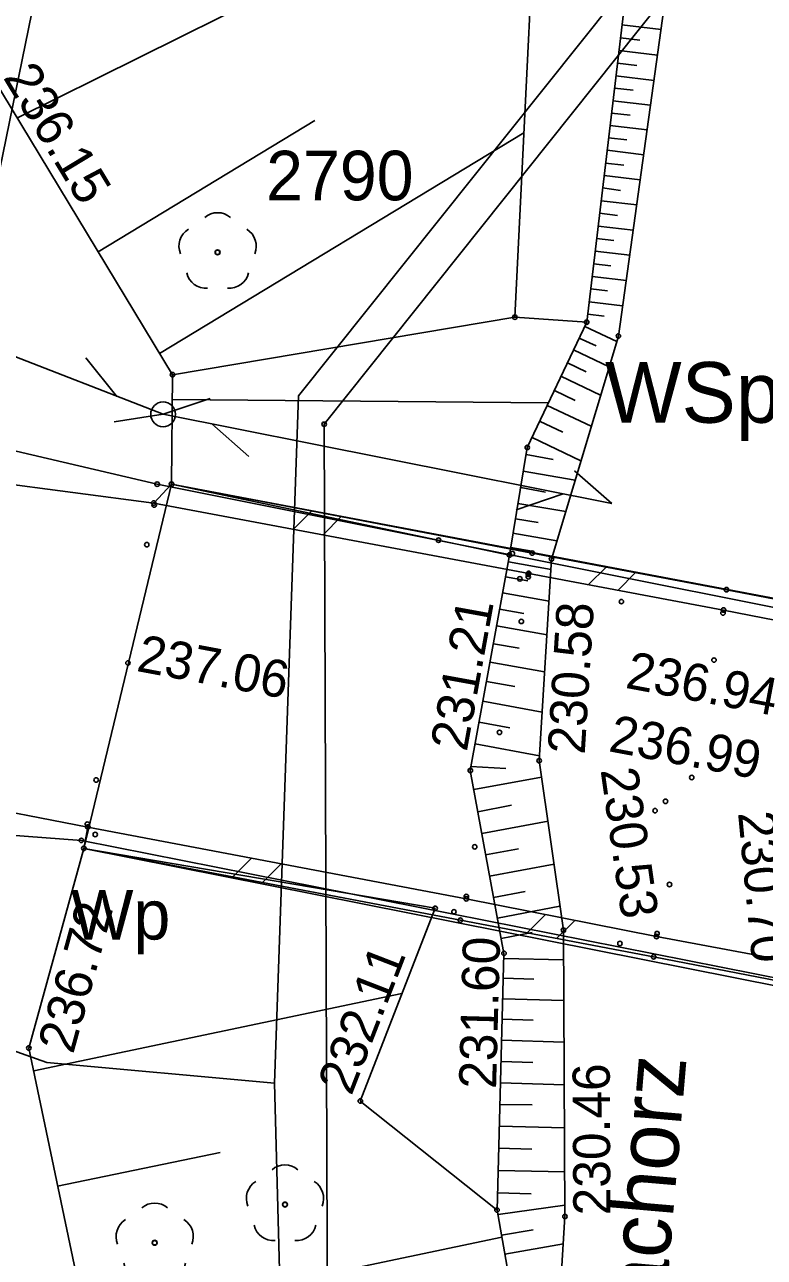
# Model space of a CAD drawing. Extents: x 6596400 to 6597200, y 5539751 to 5540251.
# Drawn here: x 6596725.66 to 6596740.59, y 5540079.28 to 5540104.16 of the extents above; entities that cross this region are included whole.
import ezdxf

# ---------------------------------------------------------------- set-up
doc = ezdxf.new("R2010")
doc.units = 0
for name, color, linetype in [('000 Inne (niezydentyfikowane)', 7, 'Continuous'), ('140-Punkty robocze', 7, 'Continuous'), ('203-punkt graniczny', 7, 'Continuous'), ('210-oznaczenie konturu użytku gruntowego', 7, 'Continuous'), ('211-numer działki ewidencyjnej', 7, 'Continuous'), ('218-kontur użytku gruntowego', 7, 'Continuous'), ('219-działka ewidencyjna', 7, 'Continuous'), ('bariera ochronna', 7, 'Continuous'), ('drzewo liściaste', 7, 'Continuous'), ('jezdnia', 7, 'Continuous'), ('Linia obszaru zagospodarowania terenu', 7, 'Continuous'), ('most', 7, 'Continuous'), ('Opis obszaru zagospodarowania terenu', 7, 'Continuous'), ('pikieta sztuczna', 7, 'Continuous'), ('pikieta sztuczna-Atr2', 7, 'Continuous'), ('przewód telekomunikacyjny napowietrzny', 7, 'Continuous'), ('skarpa nieumocniona', 7, 'Continuous'), ('skarpa umocniona', 7, 'Continuous'), ('słup przewodów napowietrznych', 7, 'Continuous'), ('woda płynąca', 7, 'Continuous'), ('woda płynąca-Atr103', 7, 'Continuous'), ('ściana oporowa (poligon)', 7, 'Continuous')]:
    doc.layers.add(name, color=color, linetype=linetype)

# ---------------------------------------------------------------- blocks, each defined once
blk = doc.blocks.new('203')
blk.add_circle((0, 0), 0.045)
blk = doc.blocks.new('SUTP')
for p, q in [((0, 0), (0.866, 0.5)), ((9.232, 0), (8.366, 0.5)), ((0, 0), (9.232, 0)), ((1.866, -0.5), (1, 0)), ((7.366, -0.5), (8.232, 0))]:
    blk.add_line(p, q)
blk = doc.blocks.new('US15')
blk.add_circle((0, 0), 0.25)
blk = doc.blocks.new('OP021')
blk.add_circle((0, 0), 0.05)
for centre, start, end in [((0, 0.4), 49.272, 130.728), ((-0.38, 0.124), 121.308, 202.548), ((0.38, 0.124), 337.452, 58.692), ((-0.235, -0.324), 193.221, 274.871), ((0.235, -0.324), 265.129, 346.779)]:
    blk.add_arc(centre, 0.4, start, end)
blk = doc.blocks.new('PIKIETA')
blk.add_circle((0, 0), 0.045)
blk = doc.blocks.new('PW01')
blk.add_circle((0, 0), 0.045)

msp = doc.modelspace()

# ---------------------------------------------------------------- linework, layer by layer
at = {"layer": '000 Inne (niezydentyfikowane)'}
for p, q in [((6596725.5, 5540102.27), (6596736, 5540107.48)), ((6596737.71, 5540104.15), (6596738.5, 5540104.06)), ((6596737.68, 5540103.89), (6596738.07, 5540103.84)), ((6596737.65, 5540103.63), (6596738.43, 5540103.54)), ((6596737.62, 5540103.38), (6596738.01, 5540103.33)), ((6596737.59, 5540103.12), (6596738.36, 5540103.03)), ((6596737.56, 5540102.87), (6596737.94, 5540102.83)), ((6596737.53, 5540102.62), (6596738.29, 5540102.53)), ((6596737.5, 5540102.37), (6596737.88, 5540102.33)), ((6596727.14, 5540099.57), (6596731.51, 5540102.22)), ((6596737.47, 5540102.12), (6596738.22, 5540102.03)), ((6596728.38, 5540097.52), (6596735.73, 5540101.97)), ((6596737.44, 5540101.87), (6596737.81, 5540101.83)), ((6596737.41, 5540101.62), (6596738.15, 5540101.53)), ((6596737.38, 5540101.36), (6596737.75, 5540101.32)), ((6596737.35, 5540101.11), (6596738.08, 5540101.02)), ((6596737.32, 5540100.86), (6596737.68, 5540100.81)), ((6596737.29, 5540100.6), (6596738.01, 5540100.52)), ((6596737.26, 5540100.35), (6596737.62, 5540100.3)), ((6596737.23, 5540100.09), (6596737.94, 5540100.01)), ((6596737.2, 5540099.84), (6596737.55, 5540099.8)), ((6596737.17, 5540099.58), (6596737.87, 5540099.5)), ((6596737.14, 5540099.33), (6596737.49, 5540099.29)), ((6596737.11, 5540099.07), (6596737.8, 5540098.99)), ((6596737.08, 5540098.82), (6596737.42, 5540098.78)), ((6596737.05, 5540098.56), (6596737.72, 5540098.48)), ((6596737.02, 5540098.31), (6596737.35, 5540098.27)), ((6596736.96, 5540098.06), (6596737.61, 5540097.76)), ((6596736.85, 5540097.83), (6596737.19, 5540097.67)), ((6596736.73, 5540097.59), (6596737.45, 5540097.25)), ((6596736.61, 5540097.33), (6596736.99, 5540097.15)), ((6596736.48, 5540097.06), (6596737.28, 5540096.68)), ((6596736.35, 5540096.77), (6596736.77, 5540096.57)), ((6596736.2, 5540096.47), (6596737.09, 5540096.05)), ((6596736.05, 5540096.15), (6596736.52, 5540095.93)), ((6596735.9, 5540095.82), (6596736.88, 5540095.35)), ((6596735.78, 5540095.48), (6596736.32, 5540095.38)), ((6596735.72, 5540095.14), (6596736.77, 5540094.96)), ((6596735.67, 5540094.81), (6596736.17, 5540094.72)), ((6596735.61, 5540094.49), (6596736.58, 5540094.33)), ((6596735.56, 5540094.18), (6596736.02, 5540094.11)), ((6596735.51, 5540093.89), (6596736.4, 5540093.74)), ((6596735.47, 5540093.6), (6596735.89, 5540093.53)), ((6596735.42, 5540093.31), (6596736.28, 5540093.16)), ((6596735.36, 5540093.01), (6596735.81, 5540092.93)), ((6596735.3, 5540092.69), (6596736.24, 5540092.52)), ((6596735.24, 5540092.36), (6596735.73, 5540092.27)), ((6596735.18, 5540092.02), (6596736.2, 5540091.84)), ((6596735.12, 5540091.66), (6596735.64, 5540091.57)), ((6596735.05, 5540091.29), (6596736.15, 5540091.09)), ((6596734.98, 5540090.9), (6596735.55, 5540090.8)), ((6596734.9, 5540090.5), (6596736.1, 5540090.28)), ((6596734.83, 5540090.08), (6596735.45, 5540089.96)), ((6596734.75, 5540089.64), (6596736.05, 5540089.4)), ((6596734.66, 5540089.18), (6596735.37, 5540089.14)), ((6596734.72, 5540088.72), (6596736.09, 5540088.97)), ((6596734.8, 5540088.27), (6596735.48, 5540088.4)), ((6596734.88, 5540087.83), (6596736.22, 5540088.08)), ((6596734.96, 5540087.4), (6596735.62, 5540087.52)), ((6596735.04, 5540086.97), (6596736.34, 5540087.21)), ((6596735.12, 5540086.54), (6596735.76, 5540086.66)), ((6596735.2, 5540086.12), (6596736.46, 5540086.36)), ((6596735.27, 5540085.71), (6596735.9, 5540085.83)), ((6596735.33, 5540085.31), (6596736.53, 5540085.28)), ((6596735.32, 5540084.91), (6596735.93, 5540084.89)), ((6596725.84, 5540083.04), (6596733.27, 5540084.6)), ((6596735.31, 5540084.49), (6596736.54, 5540084.46)), ((6596735.29, 5540084.08), (6596735.92, 5540084.06)), ((6596735.28, 5540083.66), (6596736.54, 5540083.62)), ((6596735.27, 5540083.23), (6596735.91, 5540083.21)), ((6596735.26, 5540082.8), (6596736.55, 5540082.76)), ((6596735.25, 5540082.36), (6596735.9, 5540082.35)), ((6596735.24, 5540081.92), (6596736.55, 5540081.89)), ((6596726.32, 5540080.71), (6596729.6, 5540081.39)), ((6596735.22, 5540081.48), (6596735.89, 5540081.46)), ((6596735.21, 5540081.03), (6596736.56, 5540081)), ((6596735.2, 5540080.58), (6596735.88, 5540080.56)), ((6596735.21, 5540080.14), (6596736.56, 5540080.33)), ((6596726.91, 5540077.93), (6596735.29, 5540079.68)), ((6596735.28, 5540079.72), (6596735.92, 5540079.83)), ((6596735.35, 5540079.34), (6596736.53, 5540079.55))]:
    msp.add_line(p, q, dxfattribs=at)
msp.add_lwpolyline([(6596728.64, 5540096.59), (6596736.23, 5540096.52)], dxfattribs=at)
at = {"layer": '218-kontur użytku gruntowego'}
for points in [[(6596727.34, 5540111.95), (6596725.02, 5540100.61)], [(6596725.02, 5540100.61), (6596727.34, 5540111.95)], [(6596742.6, 5540109.76), (6596731.7, 5540096.09)], [(6596731.7, 5540096.09), (6596742.6, 5540109.76)], [(6596731.7, 5540096.09), (6596731.78, 5540074)], [(6596731.78, 5540074), (6596731.7, 5540096.09)]]:
    msp.add_lwpolyline(points, dxfattribs=at)
at = {"layer": '219-działka ewidencyjna'}
for points in [[(6596725.02, 5540100.61), (6596727.34, 5540111.95)], [(6596731.7, 5540096.09), (6596742.6, 5540109.76)], [(6596731.78, 5540074), (6596731.7, 5540096.09)]]:
    msp.add_lwpolyline(points, dxfattribs=at)
at = {"layer": 'bariera ochronna'}
for points in [[(6596724.82, 5540100.27), (6596724.21, 5540095.84), (6596728.33, 5540094.88), (6596750, 5540090.55), (6596759.32, 5540088.76), (6596768.42, 5540087.04), (6596777.66, 5540085.28), (6596786.8, 5540083.5), (6596789.01, 5540083.12), (6596792.87, 5540082.26), (6596795.36, 5540081.78), (6596800.78, 5540080.9), (6596809.14, 5540079.91)], [(6596724.95, 5540083.06), (6596725.29, 5540087.8), (6596726.8, 5540087.69), (6596748.55, 5540083.38), (6596760.42, 5540081.05)]]:
    msp.add_lwpolyline(points, dxfattribs=at)
at = {"layer": 'jezdnia'}
for points in [[(6596653.124, 5540120.82), (6596653.79, 5540120.41), (6596660.56, 5540116.72), (6596663.8, 5540114.85), (6596668, 5540112.34), (6596669.54, 5540111.42), (6596675.97, 5540107.49), (6596679.93, 5540105.19), (6596682.35, 5540103.89), (6596691.43, 5540099.24), (6596702.2, 5540094.56), (6596706.34, 5540093.02), (6596710.59, 5540091.59), (6596715.92, 5540090.16), (6596720.02, 5540089.23), (6596724.29, 5540088.47), (6596726.93, 5540087.96), (6596734.57, 5540086.51), (6596738.41, 5540085.75), (6596741.83, 5540085.11), (6596743.38, 5540084.84), (6596743.64, 5540085.7), (6596748.72, 5540084.9)], [(6596828.719, 5540062.578), (6596825.42, 5540065.32), (6596821.78, 5540067.97), (6596818.46, 5540070.24), (6596813.26, 5540073.35), (6596810.44, 5540074.77), (6596805.94, 5540076.86), (6596804.14, 5540077.61), (6596801.52, 5540078.62), (6596798.28, 5540079.76), (6596795.16, 5540080.71), (6596792.67, 5540081.35), (6596788.77, 5540082.14), (6596786.6, 5540082.54), (6596777.46, 5540084.34), (6596768.21, 5540086.12), (6596759.17, 5540087.8), (6596749.8, 5540089.83), (6596749.82, 5540090.44), (6596743.18, 5540091.67), (6596739.76, 5540092.34), (6596735.83, 5540093.08), (6596728.26, 5540094.5), (6596723.35, 5540095.14)]]:
    msp.add_lwpolyline(points, dxfattribs=at)
at = {"layer": 'Linia obszaru zagospodarowania terenu'}
for points in [[(6596664.616, 5540132.112), (6596671.21, 5540127.95), (6596681.8, 5540121.54), (6596690.35, 5540115.69), (6596701.61, 5540105.97), (6596709.34, 5540098.61), (6596715.39, 5540091.82), (6596718.63, 5540088.53), (6596721.87, 5540084.71), (6596726.1, 5540083.21), (6596730.7, 5540082.79), (6596730.91, 5540075), (6596745.51, 5540074.64), (6596746.77, 5540082.74), (6596765.15, 5540085.09), (6596776.62, 5540086.27), (6596789.34, 5540086.1), (6596798.37, 5540085.54), (6596805.65, 5540083.56), (6596813.11, 5540081.53), (6596819.41, 5540077.54), (6596826.58, 5540072.81), (6596832.721, 5540067.998)], [(6596781.725, 5540112.112), (6596780.93, 5540109.34), (6596777.59, 5540106.98), (6596766.77, 5540110.34), (6596752.84, 5540119.06), (6596742.54, 5540110.89), (6596731.18, 5540096.66), (6596730.7, 5540082.79)]]:
    msp.add_lwpolyline(points, dxfattribs=at)
at = {"layer": 'most'}
msp.add_lwpolyline([(6596728.62, 5540094.88), (6596726.85, 5540087.53), (6596748.43, 5540083.24), (6596749.89, 5540090.85)], close=True, dxfattribs=at)
at = {"layer": 'skarpa nieumocniona'}
for points in [[(6596751.79, 5540118.27), (6596760.37, 5540114.69), (6596748.71, 5540116.3), (6596743.9, 5540116.21), (6596740.41, 5540117.83), (6596735.6, 5540111.55), (6596736.12, 5540109.87), (6596735.55, 5540098.25), (6596728.64, 5540097.09), (6596724.81, 5540103.41), (6596724.02, 5540108.52), (6596725.61, 5540113.6), (6596728.6, 5540116.52), (6596734.94, 5540121.2), (6596745.21, 5540121.32)], [(6596751.79, 5540118.27), (6596760.37, 5540114.69), (6596748.71, 5540116.3), (6596743.9, 5540116.21), (6596740.41, 5540117.83), (6596735.6, 5540111.55), (6596736.12, 5540109.87), (6596735.55, 5540098.25), (6596728.64, 5540097.09), (6596724.81, 5540103.41), (6596724.02, 5540108.52), (6596725.61, 5540113.6), (6596728.6, 5540116.52), (6596734.94, 5540121.2), (6596745.21, 5540121.32)], [(6596733.94, 5540086.32), (6596732.43, 5540082.43), (6596735.19, 5540080.23), (6596736.14, 5540074.83), (6596737.01, 5540060.57), (6596734.88, 5540056.12), (6596737.49, 5540048.7), (6596742.37, 5540041.71), (6596738.78, 5540039.69), (6596738.22, 5540031.96), (6596734.92, 5540032.83), (6596735.24, 5540039.91), (6596732.47, 5540046.87), (6596731.97, 5540049.93), (6596729.74, 5540057.45), (6596728.56, 5540067.81), (6596728.25, 5540071.52), (6596725.74, 5540083.5), (6596726.85, 5540087.53)], [(6596733.94, 5540086.32), (6596732.43, 5540082.43), (6596735.19, 5540080.23), (6596736.14, 5540074.83), (6596737.01, 5540060.57), (6596734.88, 5540056.12), (6596737.49, 5540048.7), (6596742.37, 5540041.71), (6596738.78, 5540039.69), (6596738.22, 5540031.96), (6596734.92, 5540032.83), (6596735.24, 5540039.91), (6596732.47, 5540046.87), (6596731.97, 5540049.93), (6596729.74, 5540057.45), (6596728.56, 5540067.81), (6596728.25, 5540071.52), (6596725.74, 5540083.5), (6596726.85, 5540087.53)]]:
    msp.add_lwpolyline(points, close=True, dxfattribs=at)
for points in [[(6596736.14, 5540074.83), (6596735.19, 5540080.23), (6596735.33, 5540085.41), (6596734.65, 5540089.1), (6596735.44, 5540093.45), (6596735.8, 5540095.62), (6596737, 5540098.15), (6596738.35, 5540109.49), (6596736.12, 5540109.87), (6596735.6, 5540111.55), (6596739.06, 5540111.12), (6596739.7, 5540112.38), (6596741.35, 5540114.97), (6596743.9, 5540116.21), (6596748.71, 5540116.3), (6596760.37, 5540114.69), (6596767.09, 5540112.87), (6596773.08, 5540108.54), (6596778.11, 5540104.44), (6596785.94, 5540101.26), (6596790.69, 5540099.45)], [(6596736.14, 5540074.83), (6596735.19, 5540080.23), (6596735.33, 5540085.41), (6596734.65, 5540089.1), (6596735.44, 5540093.45), (6596735.8, 5540095.62), (6596737, 5540098.15), (6596738.35, 5540109.49), (6596736.12, 5540109.87), (6596735.6, 5540111.55), (6596739.06, 5540111.12), (6596739.7, 5540112.38), (6596741.35, 5540114.97), (6596743.9, 5540116.21), (6596748.71, 5540116.3), (6596760.37, 5540114.69), (6596767.09, 5540112.87), (6596773.08, 5540108.54), (6596778.11, 5540104.44), (6596785.94, 5540101.26), (6596790.69, 5540099.45)], [(6596790.15, 5540098.33), (6596785.05, 5540099.81), (6596777.76, 5540103.71), (6596772.25, 5540107.73), (6596766.79, 5540112.11), (6596760.34, 5540113.97), (6596748.88, 5540115.79), (6596744.15, 5540115.57), (6596742.04, 5540114.13), (6596740.39, 5540112.04), (6596739.35, 5540110.21), (6596737.64, 5540097.87), (6596736.29, 5540093.37), (6596736.04, 5540089.3), (6596736.53, 5540085.88), (6596736.56, 5540080.1), (6596736.48, 5540078.77)], [(6596790.15, 5540098.33), (6596785.05, 5540099.81), (6596777.76, 5540103.71), (6596772.25, 5540107.73), (6596766.79, 5540112.11), (6596760.34, 5540113.97), (6596748.88, 5540115.79), (6596744.15, 5540115.57), (6596742.04, 5540114.13), (6596740.39, 5540112.04), (6596739.35, 5540110.21), (6596737.64, 5540097.87), (6596736.29, 5540093.37), (6596736.04, 5540089.3), (6596736.53, 5540085.88), (6596736.56, 5540080.1), (6596736.48, 5540078.77)]]:
    msp.add_lwpolyline(points, dxfattribs=at)
at = {"layer": 'skarpa umocniona'}
msp.add_lwpolyline([(6596735.44, 5540093.45), (6596735.8, 5540095.62), (6596737, 5540098.15), (6596735.55, 5540098.25), (6596728.64, 5540097.09), (6596728.62, 5540094.88)], close=True, dxfattribs=at)
msp.add_lwpolyline([(6596735.44, 5540093.45), (6596735.8, 5540095.62), (6596737, 5540098.15), (6596735.55, 5540098.25), (6596728.64, 5540097.09), (6596728.62, 5540094.88)], close=True, dxfattribs=at)
at = {"layer": 'woda płynąca'}
for points in [[(6596801.146, 5540105.126), (6596800.55, 5540103.15), (6596798.59, 5540101.49), (6596797.54, 5540099.56), (6596796.12, 5540099.28), (6596790.15, 5540098.33), (6596785.05, 5540099.81), (6596777.76, 5540103.71), (6596772.25, 5540107.73), (6596766.79, 5540112.11), (6596760.34, 5540113.97), (6596748.88, 5540115.79), (6596744.15, 5540115.57), (6596742.04, 5540114.13), (6596740.39, 5540112.04), (6596739.35, 5540110.21), (6596737.64, 5540097.87), (6596736.29, 5540093.37), (6596736.04, 5540089.3), (6596736.53, 5540085.88)], [(6596736.53, 5540085.88), (6596736.56, 5540080.1), (6596736.48, 5540078.77), (6596736.14, 5540074.83), (6596737.01, 5540060.57), (6596737.04, 5540056.69), (6596739.69, 5540049.9), (6596742.87, 5540042.02), (6596744.95, 5540040.49), (6596747.16, 5540032.77), (6596747.69, 5540030.285)]]:
    msp.add_lwpolyline(points, dxfattribs=at)
at = {"layer": 'ściana oporowa (poligon)'}
for points in [[(6596749.89, 5540090.85), (6596749.82, 5540090.44), (6596743.18, 5540091.67), (6596739.76, 5540092.34), (6596735.83, 5540093.08), (6596728.26, 5540094.5), (6596728.62, 5540094.88), (6596735.9, 5540093.49), (6596739.82, 5540092.75), (6596743.26, 5540092.09)], [(6596749.89, 5540090.85), (6596749.82, 5540090.44), (6596743.18, 5540091.67), (6596739.76, 5540092.34), (6596735.83, 5540093.08), (6596728.26, 5540094.5), (6596728.62, 5540094.88), (6596735.9, 5540093.49), (6596739.82, 5540092.75), (6596743.26, 5540092.09)], [(6596748.43, 5540083.24), (6596748.58, 5540083.7), (6596743.38, 5540084.84), (6596741.83, 5540085.11), (6596738.41, 5540085.75), (6596734.57, 5540086.51), (6596726.93, 5540087.96), (6596726.85, 5540087.53), (6596734.45, 5540086.08), (6596738.35, 5540085.34), (6596741.72, 5540084.69)], [(6596748.43, 5540083.24), (6596748.58, 5540083.7), (6596743.38, 5540084.84), (6596741.83, 5540085.11), (6596738.41, 5540085.75), (6596734.57, 5540086.51), (6596726.93, 5540087.96), (6596726.85, 5540087.53), (6596734.45, 5540086.08), (6596738.35, 5540085.34), (6596741.72, 5540084.69)]]:
    msp.add_lwpolyline(points, close=True, dxfattribs=at)
for points in [[(6596731.083, 5540093.97), (6596731.452, 5540094.339)], [(6596731.679, 5540093.859), (6596732.046, 5540094.226)], [(6596737.037, 5540092.853), (6596737.392, 5540093.208)], [(6596737.632, 5540092.741), (6596737.987, 5540093.096)], [(6596729.859, 5540086.956), (6596730.236, 5540087.333)], [(6596730.453, 5540086.843), (6596730.83, 5540087.22)], [(6596735.798, 5540085.824), (6596736.168, 5540086.194)], [(6596736.392, 5540085.711), (6596736.758, 5540086.077)]]:
    msp.add_lwpolyline(points, dxfattribs=at)

# ---------------------------------------------------------------- block references
at = {"layer": '140-Punkty robocze'}
for p in [(6596729.55, 5540099.56), (6596735.55, 5540098.25), (6596737, 5540098.15), (6596737.64, 5540097.87), (6596728.64, 5540097.09), (6596735.8, 5540095.62), (6596728.33, 5540094.88), (6596728.62, 5540094.88), (6596728.26, 5540094.5), (6596728.27, 5540094.46), (6596734.01, 5540093.75), (6596728.12, 5540093.66), (6596735.44, 5540093.45), (6596735.5, 5540093.48), (6596735.9, 5540093.49), (6596736.29, 5540093.37), (6596735.82, 5540093.06), (6596735.82, 5540093.01), (6596735.83, 5540093.08), (6596735.65, 5540092.97), (6596737.7, 5540092.51), (6596739.82, 5540092.75), (6596739.75, 5540092.28), (6596739.76, 5540092.34), (6596735.68, 5540092.11), (6596735.24, 5540089.87), (6596727.1, 5540088.91), (6596738.38, 5540088.29), (6596726.92, 5540088.02), (6596726.93, 5540087.96), (6596727.08, 5540087.81), (6596726.8, 5540087.69), (6596726.85, 5540087.53), (6596734.74, 5540087.56), (6596738.67, 5540086.8), (6596734.57, 5540086.56), (6596733.94, 5540086.32), (6596734.57, 5540086.51), (6596734.32, 5540086.25), (6596734.45, 5540086.08), (6596736.53, 5540085.88), (6596738.42, 5540085.81), (6596737.67, 5540085.61), (6596738.41, 5540085.75), (6596738.35, 5540085.34), (6596725.74, 5540083.5), (6596732.43, 5540082.43), (6596730.91, 5540080.34), (6596735.19, 5540080.23), (6596736.56, 5540080.1), (6596728.28, 5540079.57)]:
    msp.add_blockref('PIKIETA', p, dxfattribs=at)
at = {"layer": '203-punkt graniczny'}
msp.add_blockref('203', (6596731.7, 5540096.09), dxfattribs=at)
at = {"layer": 'drzewo liściaste'}
for p in [(6596729.55, 5540099.56), (6596730.91, 5540080.34), (6596728.28, 5540079.57)]:
    msp.add_blockref('OP021', p, dxfattribs=at)
at = {"layer": 'pikieta sztuczna'}
for p in [(6596727.74, 5540091.27), (6596739.57, 5540091.33), (6596736.04, 5540089.3), (6596734.65, 5540089.1), (6596739.12, 5540088.96), (6596738.59, 5540088.48), (6596735.33, 5540085.41), (6596725.74, 5540083.5), (6596732.43, 5540082.43), (6596736.56, 5540080.1)]:
    msp.add_blockref('PW01', p, dxfattribs=at)
at = {"layer": 'przewód telekomunikacyjny napowietrzny'}
for rotation in [158.745, -11.235999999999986]:
    msp.add_blockref('SUTP', (6596728.45, 5540096.29), dxfattribs=dict(at, rotation=rotation))
at = {"layer": 'słup przewodów napowietrznych'}
msp.add_blockref('US15', (6596728.45, 5540096.29), dxfattribs=at)

# ---------------------------------------------------------------- texts
at = {"layer": '210-oznaczenie konturu użytku gruntowego'}
msp.add_text('Wp', height=1, dxfattribs=at).set_placement((6596726.59, 5540085.69))
at = {"layer": '211-numer działki ewidencyjnej'}
msp.add_text('2790', height=1, dxfattribs=at).set_placement((6596730.53, 5540100.61))
at = {"layer": 'Opis obszaru zagospodarowania terenu'}
msp.add_text('WSp12', height=1.225, dxfattribs=at).set_placement((6596737.37, 5540096.12))
at = {"layer": 'pikieta sztuczna-Atr2'}
for s, rotation, p in [('236.15', 301.216, (6596725.209, 5540103.091)), ('231.21', 79.707, (6596734.578, 5540089.466)), ('230.58', 86.485, (6596736.959, 5540089.414)), ('237.06', 349.376, (6596727.892, 5540091.113)), ('236.94', 349.336, (6596737.761, 5540090.773)), ('236.99', 349.336, (6596737.421, 5540089.493)), ('230.53', 278.154, (6596737.278, 5540089.114)), ('230.70', 275.417, (6596740.053, 5540088.249)), ('236.72', 74.601, (6596726.633, 5540083.361)), ('231.60', 88.452, (6596735.17, 5540082.67)), ('232.11', 68.785, (6596732.249, 5540082.519)), ('230.46', 90.297, (6596737.48, 5540080.124))]:
    msp.add_text(s, height=0.75, rotation=rotation, dxfattribs=at).set_placement(p)
at = {"layer": 'woda płynąca-Atr103'}
msp.add_text('Bachorz', height=1.25, rotation=85.068, dxfattribs=at).set_placement((6596738.49, 5540077.19))
msp.add_text('Bachorz', height=1.25, rotation=85.068, dxfattribs=at).set_placement((6596738.49, 5540077.19))
msp.add_text('Bachorz', height=1.25, rotation=85.068, dxfattribs=at).set_placement((6596738.49, 5540077.19))

doc.saveas('drawing.dxf')
